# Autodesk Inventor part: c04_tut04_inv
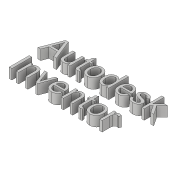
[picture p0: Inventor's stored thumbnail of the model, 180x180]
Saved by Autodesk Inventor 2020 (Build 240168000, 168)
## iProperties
Created: 2017-04
Part Number: c04_tut04_inv
Material: Generic
Document SubType Name: Modeling
Designer: CADCIM 00
Density: 1 g/cm^3
Appearance: Default
Author: CADCIM 00
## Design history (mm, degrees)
sketch "Sketch1"
  geometry: L1 (0.506, 21.792)-(30.182, 21.792); L2 (30.182, 21.792)-(30.182, 9.249); L3 (30.182, 9.249)-(0.506, 9.249); L4 (0.506, 9.249)-(0.506, 21.792); 1 further point
  constraints: 2 other
extrude "Extrusion1" new body sketch "Sketch1" distance "d0" = 2.5; taper "d1" = 0 deg
body "Solid1"
